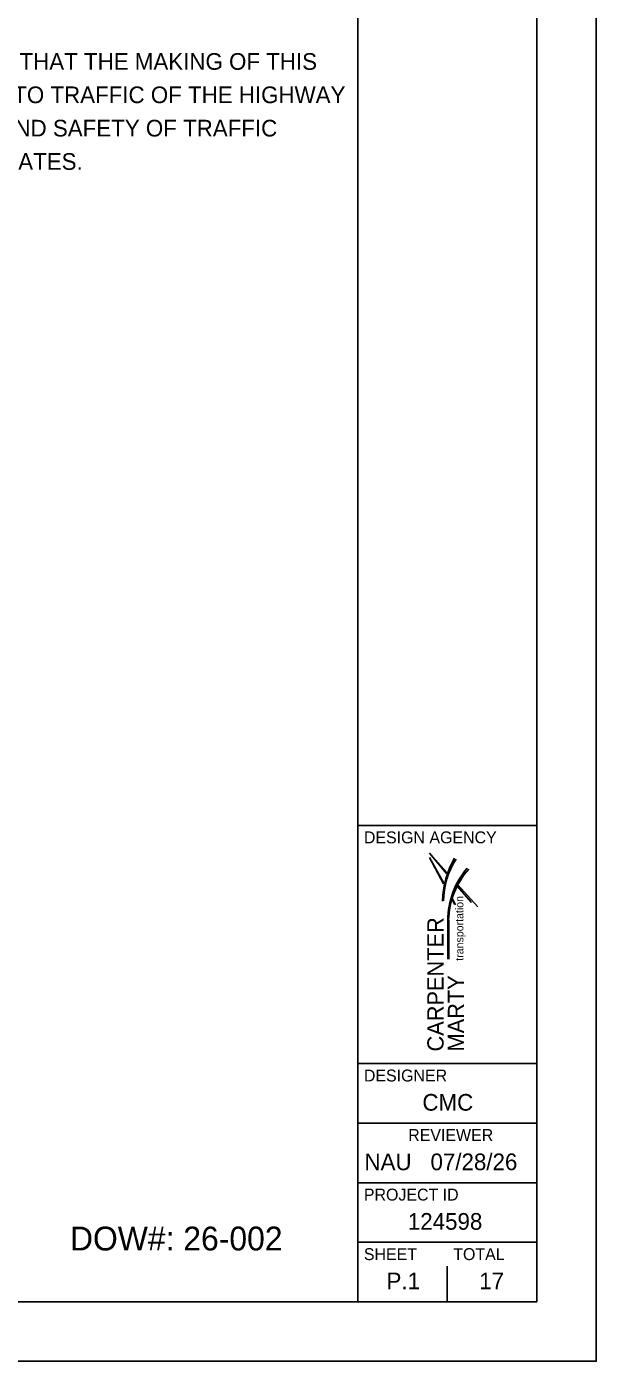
# Model space of a CAD drawing. Extents: x 0 to 34, y 0 to 22.
# Drawn here: x 29.22 to 34, y 0 to 11.21 of the extents above; entities that cross this region are included whole.
import ezdxf

# ---------------------------------------------------------------- set-up
doc = ezdxf.new("R2010")
doc.units = 0
for name, color, linetype in [('SH_Border', 7, 'Continuous'), ('SH_Cut_Line', 7, 'Continuous'), ('SH_Data', 7, 'Continuous'), ('SH_Text', 7, 'Continuous')]:
    doc.layers.add(name, color=color, linetype=linetype)

msp = doc.modelspace()

# ---------------------------------------------------------------- linework, layer by layer
at = {"layer": 'SH_Border'}
for p, q in [((32, 0.5), (32, 21.5)), ((32, 4.5), (33.5, 4.5)), ((32, 2.5), (33.5, 2.5)), ((32, 2), (33.5, 2)), ((32, 1.5), (33.5, 1.5)), ((32, 1), (33.5, 1))]:
    msp.add_line(p, q, dxfattribs=at)
msp.add_lwpolyline([(1.5, 21.5), (33.5, 21.5), (33.5, 0.5), (1.5, 0.5)], close=True, dxfattribs=at)
at = {"layer": 'SH_Cut_Line'}
msp.add_lwpolyline([(0, 0), (34, 0), (34, 22), (0, 22)], close=True, dxfattribs=at)
at = {"layer": 'SH_Data'}
for p, q in [((32.75, 3.5), (32.75, 3.5)), ((32.75, 0.5), (32.75, 0.8)), ((32.375, 0.675), (32.375, 0.675))]:
    msp.add_line(p, q, dxfattribs=at)
at = {"layer": 'SH_Text'}
for p, q in [((32.721, 4.016), (32.602, 4.232)), ((32.952, 3.853), (32.834, 3.991)), ((32.839, 4.002), (33.006, 3.816)), ((32.811, 3.84), (32.79, 3.88)), ((32.82, 3.834), (32.791, 3.886)), ((32.755, 3.378), (32.755, 3.704)), ((32.762, 3.378), (32.762, 3.704))]:
    msp.add_line(p, q, dxfattribs=at)
for points in [[(32.746, 4.104), (32.601, 4.266)], [(32.601, 4.266), (32.744, 4.098)], [(32.721, 4.016), (32.602, 4.232)], [(32.602, 4.232), (32.719, 4.011)]]:
    msp.add_lwpolyline(points, dxfattribs=at)
for centre, radius, start, end in [((33.432, 3.86), 0.721, 149.5704, 179.5529), ((33.373, 3.862), 0.654, 147.1423, 179.6525), ((33.426, 3.704), 0.671, 139.2898, 180.0106), ((33.433, 3.688), 0.672, 138.5126, 178.6075)]:
    msp.add_arc(centre, radius, start, end, dxfattribs=at)

# ---------------------------------------------------------------- texts
at = {"layer": 'SH_Data'}
for s, height, p in [(' I HEREBY APPROVE THESE PLANS AND DECLARE THAT THE MAKING OF THIS', 0.14, (24.5, 10.846)), ('IMPROVEMENT WILL NOT REQUIRE THE CLOSING TO TRAFFIC OF THE HIGHWAY', 0.14, (24.5, 10.566)), ('AND THAT PROVISIONS FOR THE MAINTENANCE AND SAFETY OF TRAFFIC', 0.14, (24.5, 10.286)), ('WILL BE AS SET FORTH ON THE PLANS AND ESTIMATES.', 0.14, (24.5, 10.006)), ('DESIGN AGENCY', 0.1, (32.05, 4.35)), ('DESIGNER', 0.1, (32.05, 2.35)), ('CMC', 0.14, (32.541, 2.105)), ('REVIEWER', 0.1, (32.422, 1.85)), ('NAU', 0.14, (32.055, 1.605)), ('07/28/26', 0.14, (32.609, 1.605)), ('PROJECT ID', 0.1, (32.05, 1.35)), ('124598', 0.14, (32.419, 1.105)), ('SHEET', 0.1, (32.05, 0.85)), ('TOTAL', 0.1, (32.8, 0.85)), ('P.1', 0.14, (32.24, 0.605)), ('17', 0.14, (33.018, 0.605))]:
    msp.add_text(s, height=height, dxfattribs=at).set_placement(p)
at = {"layer": 'SH_Text'}
for s, height, p in [('transportation', 0.06649, (32.885, 3.364)), ('CARPENTER ', 0.1367, (32.719, 2.602)), ('MARTY', 0.1367, (32.891, 2.602))]:
    msp.add_text(s, height=height, rotation=90, dxfattribs=at).set_placement(p)
msp.add_text('DOW#: 26-002', height=0.2, dxfattribs=at).set_placement((29.584, 0.931))

doc.saveas('drawing.dxf')
